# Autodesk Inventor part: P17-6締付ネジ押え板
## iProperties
Shininess: 64.0
Length Units: 11269
Angle Units: 11279
Time Units: 11290
Mass Units: 11284
Length Display Precision: 2
Angle Display Precision: 1
Created: 2002-10
Part Number: P17-6締付ネジ押え板
Document SubType Name: ﾓﾃﾞﾘﾝｸﾞ
Designer: 株式会社富士システム
Stock Number: P17-6締付ネジ押え板
Density: 1 g/cm^3
Density: 0.0
Volumn: 0.0
Area: 0.0
PropertySet Name: Model Information
Control State: 0
Master: False
Checked Out: False
Author: 株式会社富士システム
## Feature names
1. 押し出し1 [Extrusion]
2. 押し出し2 [Extrusion]
3. 押し出し3 [Extrusion]
